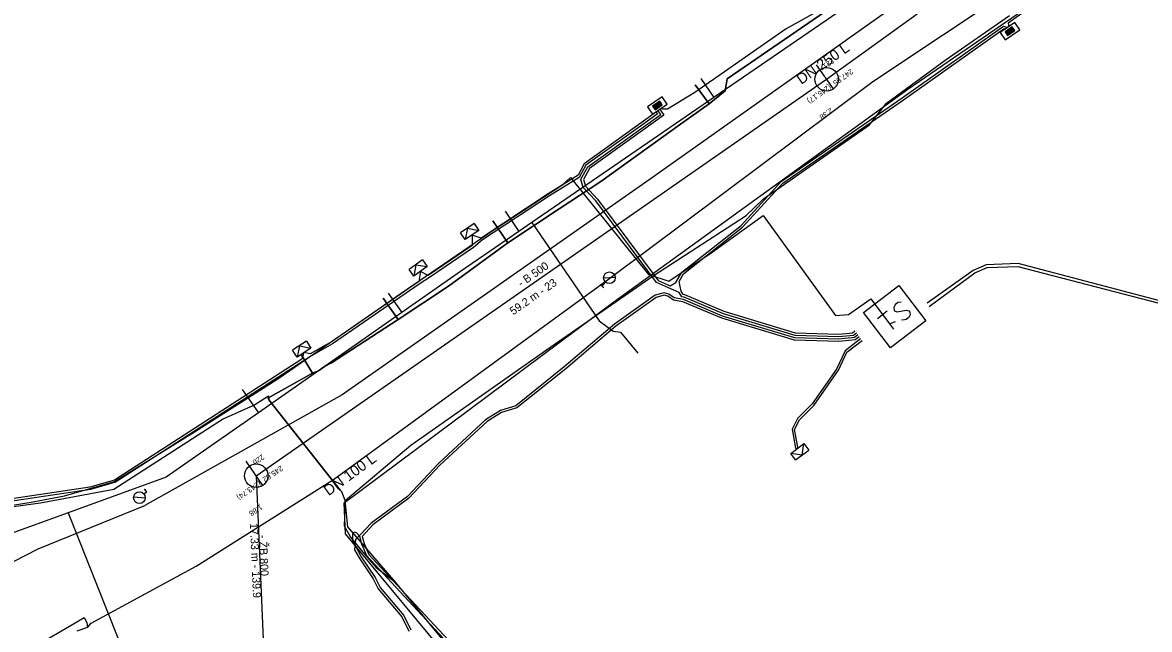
# Model space of a CAD drawing. Extents: x -600636 to -600148, y -1203980 to -1203569.
# Drawn here: x -600579.1 to -600483.1, y -1203791.8 to -1203740.1 of the extents above; entities that cross this region are included whole.
import ezdxf

# ---------------------------------------------------------------- set-up
doc = ezdxf.new("R2010")
doc.units = 0
for name, color, linetype in [('Cetin zam průběh', 7, 'Continuous'), ('EON objekty', 7, 'Continuous'), ('EON podzemní NN', 7, 'Continuous'), ('EON podzemní VN', 7, 'Continuous'), ('GasNet NTL', 7, 'Continuous'), ('Implicitní', 7, 'Continuous'), ('VaK Břeclav_kanalizace', 7, 'Continuous'), ('Vak Břeclav_vodovod', 7, 'Continuous'), ('Vrstva 6', 7, 'Continuous'), ('Vrstva 9', 7, 'Continuous')]:
    doc.layers.add(name, color=color, linetype=linetype)

# ---------------------------------------------------------------- blocks, each defined once
blk = doc.blocks.new('NN630')
at = {"layer": 'Vrstva 9'}
for points in [[(-0.003, -0.7), (-0.703, 0)], [(-0.703, -0.7), (-0.703, 0), (0.697, 0), (0.697, -0.7)], [(-0.703, -0.7), (0.697, -0.7)], [(-0.003, -0.7), (0.697, 0)]]:
    blk.add_lwpolyline(points, dxfattribs=at)
blk = doc.blocks.new('NN620')
at = {"layer": 'EON objekty'}
for points in [[(0.752, 0.004), (-0.748, 0.004)], [(-0.748, 0.004), (-0.748, -0.746)], [(0.752, -0.746), (0.752, 0.004)], [(-0.748, -0.746), (0.752, -0.746)], [(0.368, -0.18), (-0.376, -0.18)], [(-0.376, -0.18), (-0.376, -0.558)], [(-0.376, -0.558), (0.368, -0.558)], [(0.321, -0.227), (-0.329, -0.227)], [(-0.329, -0.227), (-0.329, -0.51)], [(-0.329, -0.51), (0.321, -0.51)], [(0.274, -0.274), (-0.281, -0.274)], [(-0.281, -0.274), (-0.281, -0.463)], [(-0.281, -0.463), (0.274, -0.463)], [(0.227, -0.321), (-0.234, -0.321)], [(-0.234, -0.321), (-0.234, -0.416)], [(-0.234, -0.416), (0.227, -0.416)], [(-0.193, -0.369), (0.185, -0.369)], [(0.227, -0.416), (0.227, -0.321)], [(0.274, -0.463), (0.274, -0.274)], [(0.321, -0.51), (0.321, -0.227)], [(0.368, -0.558), (0.368, -0.18)]]:
    blk.add_lwpolyline(points, dxfattribs=at)
blk = doc.blocks.new('VN640')
at = {"layer": 'Vrstva 6'}
for points in [[(-1.89, 1.889), (1.889, 1.889)], [(-1.89, -1.89), (-1.89, 1.889)], [(1.889, 1.889), (1.889, -1.89)], [(-1.26, 0.787), (-0.221, 0.787)], [(-0.725, 0.787), (-0.725, -0.788)], [(1.197, 0.661), (0.945, 0.787), (0.661, 0.787), (0.409, 0.661), (0.283, 0.472), (0.283, 0.409), (0.409, 0.22), (1.133, -0.158), (1.259, -0.316), (1.259, -0.473), (1.133, -0.662), (0.913, -0.788), (0.629, -0.788), (0.503, -0.725), (0.283, -0.599)], [(1.889, -1.89), (-1.89, -1.89)]]:
    blk.add_lwpolyline(points, dxfattribs=at)
blk = doc.blocks.new('MoSymbol 2')
at = {"layer": 'Implicitní'}
blk.add_line((0, 0.0005), (0, -0.00075), dxfattribs=at)
blk.add_circle((0, 0), 0.0005, dxfattribs=at)
blk = doc.blocks.new('MoSymbol 3')
at = {"layer": 'Implicitní'}
for p, q in [((-0.000365, -0.000365), (0.000365, 0.000365)), ((-0.000225, 0.00095), (0.000225, 0.00095)), ((0, 0.00095), (0, 0.0005))]:
    blk.add_line(p, q, dxfattribs=at)
blk.add_circle((0, 0), 0.0005, dxfattribs=at)
blk = doc.blocks.new('MoSymbol 4')
at = {"layer": 'Implicitní'}
for p, q in [((-0.000365, -0.000365), (0.000365, 0.000365)), ((0.0003, -0.0008), (0.0002, -0.00085))]:
    blk.add_line(p, q, dxfattribs=at)
blk.add_lwpolyline([(0, -0.0005), (0, -0.0008), (0.0003, -0.0008), (0.0002, -0.00075)], dxfattribs=at)
blk.add_circle((0, 0), 0.0005, dxfattribs=at)

msp = doc.modelspace()

# ---------------------------------------------------------------- linework, layer by layer
at = {"layer": 'Cetin zam průběh'}
for points in [[(-600506.23, -1203736.22), (-600510.74, -1203739.23), (-600519.05, -1203744.93), (-600519.22, -1203745.96), (-600520.6, -1203747.08), (-600523.03, -1203748.81), (-600529.84, -1203753.68), (-600533.39, -1203756), (-600537.76, -1203758.9), (-600542.81, -1203762.61), (-600547.1, -1203765.43), (-600552.78, -1203769.13), (-600553.37, -1203769.45), (-600553.89, -1203769.82), (-600554.42, -1203770.01), (-600558.01, -1203772.02)], [(-600499.06, -1203830.56), (-600501.19, -1203829.34), (-600520.52, -1203816.59), (-600528.18, -1203809.84), (-600537.51, -1203800.68), (-600551.58, -1203783.7), (-600551.71, -1203781.06), (-600528.73, -1203763.94), (-600503.65, -1203745.81), (-600492.34, -1203738.04), (-600490.82, -1203737.26)], [(-600551.61, -1203780.87), (-600546.02, -1203776.14), (-600534.46, -1203768.01), (-600525.37, -1203761.73), (-600517.43, -1203756.57), (-600515.95, -1203755.15), (-600506.94, -1203748.87), (-600505.47, -1203747), (-600500.48, -1203743.35), (-600495, -1203739.53)], [(-600520.6, -1203747.08), (-600519.22, -1203745.96), (-600519.05, -1203744.93), (-600510.74, -1203739.23)], [(-600521.78, -1203745.45), (-600520.6, -1203747.08)], [(-600520.6, -1203747.08), (-600521.78, -1203745.45)], [(-600537.76, -1203758.9), (-600533.39, -1203756), (-600529.84, -1203753.68), (-600523.03, -1203748.81), (-600520.6, -1203747.08)], [(-600539.032, -1203757.042), (-600537.76, -1203758.9)], [(-600537.76, -1203758.9), (-600539.032, -1203757.042)], [(-600547.1, -1203765.43), (-600542.81, -1203762.61), (-600537.76, -1203758.9)], [(-600548.377, -1203763.622), (-600547.1, -1203765.43)], [(-600547.1, -1203765.43), (-600548.377, -1203763.622)], [(-600553.37, -1203769.45), (-600552.78, -1203769.13), (-600547.1, -1203765.43)], [(-600555.386, -1203768.434), (-600554.42, -1203770.01)], [(-600554.42, -1203770.01), (-600555.386, -1203768.434)], [(-600558.18, -1203772.12), (-600558.01, -1203772.02), (-600554.42, -1203770.01)], [(-600554.42, -1203770.01), (-600553.89, -1203769.82), (-600553.37, -1203769.45)], [(-600587.64, -1203782.42), (-600577.59, -1203781.05), (-600571.34, -1203779.9), (-600562.09, -1203773.93), (-600559.42, -1203772.74), (-600558.16, -1203771.94), (-600558.14, -1203772.28)], [(-600558.14, -1203772.28), (-600558.18, -1203772.12)], [(-600558.14, -1203772.28), (-600552.05, -1203779.98)], [(-600551.61, -1203780.87), (-600551.92, -1203780.12), (-600552.05, -1203779.98), (-600558.14, -1203772.28)], [(-600577.59, -1203781.05), (-600571.34, -1203779.9)], [(-600551.61, -1203780.87), (-600551.71, -1203783.02)], [(-600547.3, -1203787.83), (-600551.39, -1203783.09), (-600551.61, -1203780.87)], [(-600551.71, -1203783.02), (-600551.17, -1203783.97)], [(-600551.17, -1203783.97), (-600549.98, -1203785.44)], [(-600549.98, -1203785.44), (-600548.99, -1203786.57)], [(-600548.99, -1203786.57), (-600547.3, -1203787.83)], [(-600531.56, -1203806.25), (-600532.29, -1203804.48), (-600533.68, -1203802.64), (-600539.8, -1203796.23), (-600541.55, -1203794.83), (-600547.3, -1203787.83)]]:
    msp.add_lwpolyline(points, dxfattribs=at)
at = {"layer": 'EON podzemní NN'}
for points in [[(-600492.79, -1203738.54), (-600495.12, -1203740.2), (-600495.048, -1203740.497)], [(-600510.522, -1203738.712), (-600514.041, -1203740.671), (-600521.805, -1203746.093), (-600524.15, -1203747.521), (-600524.559, -1203747.517), (-600524.638, -1203747.401)], [(-600524.803, -1203747.515), (-600524.45, -1203748.027), (-600525.161, -1203748.537), (-600530.795, -1203752.578), (-600531.314, -1203753.511), (-600531.149, -1203754.093), (-600530.101, -1203755.202), (-600524.951, -1203762.125), (-600523.912, -1203762.574), (-600523.438, -1203762.281), (-600522.938, -1203761.404), (-600517.882, -1203757.418), (-600514.454, -1203753.685), (-600504.155, -1203746.549), (-600495.501, -1203740.461), (-600495.161, -1203740.575)], [(-600508.174, -1203766.439), (-600508.374, -1203766.595), (-600509.556, -1203766.723), (-600513.237, -1203766.614), (-600519.313, -1203764.765), (-600522.658, -1203763.34), (-600522.814, -1203763.315), (-600522.985, -1203763.029), (-600523.058, -1203762.627), (-600523.155, -1203762.189), (-600522.784, -1203761.536), (-600517.746, -1203757.566), (-600514.322, -1203753.837), (-600504.041, -1203746.713), (-600495.441, -1203740.663), (-600495.347, -1203740.703)], [(-600525.132, -1203747.742), (-600525.004, -1203747.932), (-600525.449, -1203748.251), (-600531.101, -1203752.305), (-600531.678, -1203753.342), (-600534.216, -1203754.907), (-600539.903, -1203758.664), (-600540.687, -1203759.293), (-600544.438, -1203761.852), (-600545.238, -1203762.368), (-600552.695, -1203767.501), (-600554.501, -1203768.539), (-600555.203, -1203768.985), (-600571.205, -1203779.307), (-600573.331, -1203779.913), (-600584.423, -1203781.578), (-600586.99, -1203781.825)], [(-600525.297, -1203747.856), (-600525.279, -1203747.883), (-600531.254, -1203752.169), (-600531.757, -1203753.151), (-600534.324, -1203754.739), (-600540.021, -1203758.502), (-600540.809, -1203758.243), (-600540.807, -1203759.133), (-600544.548, -1203761.686), (-600545.191, -1203761.339), (-600545.348, -1203762.202), (-600552.801, -1203767.331), (-600554.605, -1203768.367), (-600555.135, -1203768.259), (-600555.311, -1203768.817), (-600571.289, -1203779.123), (-600573.373, -1203779.717), (-600584.447, -1203781.38), (-600586.729, -1203781.599)], [(-600508.051, -1203766.597), (-600508.296, -1203766.788), (-600509.548, -1203766.923), (-600513.27, -1203766.813), (-600519.381, -1203764.953), (-600522.714, -1203763.534), (-600522.937, -1203763.499), (-600523.15, -1203763.143), (-600524.054, -1203762.728), (-600525.079, -1203762.287), (-600530.255, -1203755.33), (-600531.329, -1203754.195), (-600531.529, -1203753.485), (-600530.948, -1203752.441), (-600524.726, -1203747.979), (-600524.968, -1203747.629)], [(-600507.93, -1203766.757), (-600508.218, -1203766.98), (-600509.54, -1203767.123), (-600513.302, -1203767.013), (-600519.449, -1203765.141), (-600522.77, -1203763.728), (-600523.568, -1203763.602), (-600524.04, -1203763.278), (-600524.429, -1203763.174), (-600525.201, -1203763.374), (-600528.66, -1203765.841), (-600532.953, -1203769.48), (-600537.072, -1203772.794), (-600538.387, -1203773.179), (-600539.651, -1203773.979), (-600543.651, -1203777.673), (-600546.318, -1203780.515), (-600549.403, -1203782.78), (-600550.274, -1203783.739), (-600550.742, -1203784.175), (-600550.814, -1203785.049), (-600550.442, -1203785.747), (-600549.233, -1203787.52), (-600548.817, -1203788.369), (-600546.802, -1203790.768), (-600546.203, -1203791.975)], [(-600507.807, -1203766.914), (-600508.14, -1203767.173), (-600509.532, -1203767.323), (-600513.335, -1203767.212), (-600519.517, -1203765.329), (-600522.826, -1203763.922), (-600523.644, -1203763.792), (-600524.125, -1203763.462), (-600524.429, -1203763.38), (-600525.115, -1203763.558), (-600528.538, -1203765.999), (-600532.825, -1203769.634), (-600536.978, -1203772.974), (-600538.303, -1203773.363), (-600539.529, -1203774.139), (-600543.511, -1203777.815), (-600546.184, -1203780.665), (-600549.269, -1203782.93), (-600550.165, -1203783.917), (-600550.015, -1203784.513), (-600549.597, -1203785.445), (-600546.825, -1203788.464), (-600540.809, -1203794.912)], [(-600507.684, -1203767.072), (-600509.013, -1203768.103), (-600509.737, -1203769.669), (-600511.828, -1203772.631), (-600513.052, -1203773.88), (-600513.528, -1203774.769), (-600513.229, -1203776.405), (-600513.085, -1203776.425), (-600513.041, -1203776.319), (-600513.318, -1203774.801), (-600512.89, -1203774), (-600511.674, -1203772.759), (-600509.563, -1203769.769), (-600508.852, -1203768.232), (-600507.561, -1203767.229)], [(-600540.961, -1203795.042), (-600546.971, -1203788.6), (-600549.767, -1203785.557), (-600550.205, -1203784.579), (-600550.366, -1203783.937), (-600550.644, -1203783.623), (-600550.862, -1203783.55), (-600550.993, -1203783.691), (-600551.002, -1203784.225), (-600550.27, -1203785.645), (-600549.059, -1203787.42), (-600548.649, -1203788.259), (-600546.634, -1203790.658), (-600546.033, -1203791.869)]]:
    msp.add_lwpolyline(points, dxfattribs=at)
at = {"layer": 'EON podzemní VN'}
for points in [[(-600587.683, -1203782.424), (-600583.35, -1203781.8), (-600578.39, -1203781.01), (-600575.54, -1203780.47), (-600571.28, -1203779.25), (-600564.47, -1203775), (-600557.37, -1203770.49), (-600546.85, -1203763.19), (-600538.93, -1203757.78), (-600533.07, -1203753.94), (-600532.42, -1203753.34), (-600525.77, -1203761.6), (-600524.04, -1203762.18), (-600520.34, -1203759.69), (-600515.99, -1203756.58), (-600509.828, -1203765.1), (-600508.705, -1203765.014), (-600506.819, -1203763.668), (-600505.22, -1203765.813), (-600504.7, -1203765.596)], [(-600480.143, -1203764.381), (-600494.25, -1203760.681), (-600496.996, -1203760.787), (-600498.081, -1203761.253), (-600502, -1203764.039)], [(-600501.847, -1203764.325), (-600497.959, -1203761.475), (-600496.908, -1203761.001), (-600494.282, -1203760.923), (-600480.162, -1203764.577), (-600479.132, -1203764.829), (-600476.382, -1203766.071), (-600473.11, -1203766.482), (-600465.75, -1203768.323), (-600457.511, -1203769.594), (-600456.508, -1203769.518), (-600454.624, -1203770.445), (-600451.211, -1203771.488), (-600448.233, -1203771.815), (-600444.486, -1203774.019), (-600442.217, -1203775.59), (-600438.167, -1203778.496), (-600424.472, -1203787.735), (-600416.801, -1203792.528), (-600411.123, -1203796.487), (-600404.975, -1203801.537), (-600404.82, -1203801.644), (-600404.96, -1203802.62)]]:
    msp.add_lwpolyline(points, dxfattribs=at)
at = {"layer": 'GasNet NTL'}
for points in [[(-600486.68, -1203722.48), (-600489.25, -1203724.39), (-600497.78, -1203730.73), (-600501.03, -1203733.15), (-600504.95, -1203736.06), (-600509.64, -1203739.28), (-600520.2, -1203746.52), (-600535.72, -1203757.18), (-600536.81, -1203757.93), (-600541.8, -1203761.35), (-600546.79, -1203764.85), (-600559, -1203773.38), (-600566.88, -1203778.88), (-600575.24, -1203781.91), (-600588.36, -1203786.65), (-600589.51, -1203786.96)], [(-600521.31, -1203744.92), (-600520.2, -1203746.52)], [(-600537.99, -1203756.21), (-600536.81, -1203757.93)], [(-600535.72, -1203757.18), (-600529.98, -1203765.55), (-600528.77, -1203766.42), (-600528.15, -1203766.53), (-600526.67, -1203768.32)], [(-600547.95, -1203763.19), (-600546.79, -1203764.85)], [(-600560.39, -1203771.4), (-600559, -1203773.38)], [(-600575.24, -1203781.91), (-600569.42, -1203796.55), (-600565.52, -1203798.53), (-600556.3, -1203803.23), (-600544.92, -1203810.5), (-600533.6, -1203818.43), (-600528.85, -1203821.76), (-600523.82, -1203825.28), (-600521.43, -1203826.96)]]:
    msp.add_lwpolyline(points, dxfattribs=at)
at = {"layer": 'VaK Břeclav_kanalizace'}
for p, q in [((-600510.583, -1203744.976), (-600486.459, -1203727.53)), ((-600559.203, -1203778.746), (-600510.583, -1203744.976)), ((-600559.203, -1203778.746), (-600558.458, -1203796.062))]:
    msp.add_line(p, q, dxfattribs=at)
at = {"layer": 'Vak Břeclav_vodovod'}
msp.add_line((-600573.583, -1203791.689), (-600574.494, -1203791.995), dxfattribs=at)
for points in [[(-600454.254, -1203701.013), (-600472.203, -1203715.152), (-600488.658, -1203727.344), (-600496.91, -1203733.124), (-600525.432, -1203753.341), (-600551.886, -1203771.847), (-600568.695, -1203781.296)], [(-600529.075, -1203761.905), (-600506.647, -1203745.162), (-600494.673, -1203737.188), (-600466.586, -1203717.369), (-600450.006, -1203704.697)], [(-600573.583, -1203791.689), (-600573.278, -1203791.312), (-600564.325, -1203786.439), (-600552.62, -1203779.071), (-600529.075, -1203761.905)], [(-600612.162, -1203773.201), (-600602.995, -1203784.637), (-600601.189, -1203803.343), (-600600.899, -1203803.294), (-600597.986, -1203803.077), (-600584.599, -1203797.079), (-600575.117, -1203791.572), (-600573.857, -1203790.834), (-600573.636, -1203791.26), (-600573.583, -1203791.689)], [(-600600.849, -1203803.933), (-600600.899, -1203803.294), (-600601.584, -1203796.186), (-600600.078, -1203795.751), (-600587.99, -1203790.2), (-600577.783, -1203784.972), (-600568.695, -1203781.296)]]:
    msp.add_lwpolyline(points, dxfattribs=at)

# ---------------------------------------------------------------- block references
at = {"layer": 'EON podzemní NN'}
for name, p, rotation in [('NN620', (-600495.16, -1203740.575), 34.499191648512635), ('NN620', (-600524.804, -1203747.514), -145.40948332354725), ('NN630', (-600540.809, -1203758.243), -145.68219166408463), ('NN630', (-600545.191, -1203761.339), -144.19583613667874), ('NN630', (-600555.135, -1203768.259), -146.84598330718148), ('NN630', (-600513.085, -1203776.425), 36.87192492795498)]:
    msp.add_blockref(name, p, dxfattribs=dict(at, rotation=rotation))
at = {"layer": 'EON podzemní VN', "rotation": 37.35362222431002}
msp.add_blockref('VN640', (-600504.779, -1203765.202), dxfattribs=at)
at = {"layer": 'VaK Břeclav_kanalizace'}
for p, xscale, yscale, rotation in [((-600510.583, -1203744.976), 1999.750031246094, 1999.7500312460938, -144.72778475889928), ((-600559.203, -1203778.746), 1999.7500312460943, 1999.7500312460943, -145.4726226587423)]:
    msp.add_blockref('MoSymbol 2', p, dxfattribs=dict(at, xscale=xscale, yscale=yscale, rotation=rotation))
at = {"layer": 'Vak Břeclav_vodovod'}
for name, p, xscale, yscale, rotation in [('MoSymbol 3', (-600529.097, -1203761.885), 999.875015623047, 999.8750156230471, 138.37882730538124), ('MoSymbol 4', (-600569.159, -1203780.618), 999.8750156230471, 999.875015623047, 129.01940047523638)]:
    msp.add_blockref(name, p, dxfattribs=dict(at, xscale=xscale, yscale=yscale, rotation=rotation))

# ---------------------------------------------------------------- texts
at = {"layer": 'VaK Břeclav_kanalizace'}
for s, height, rotation, p in [('221', 0.4549, 215.27222, (-600510.132, -1203743.157)), ('247,55  (245,17)', 0.45494, 215.27222, (-600508.529, -1203744.066)), ('2.38', 0.4549, 215.27222, (-600510.253, -1203747.385)), ('- B 500', 0.6824, 34.78271, (-600536.621, -1203762.71)), ('59.2 m - 23', 0.68241, 34.78271, (-600537.3, -1203765.094)), ('22b', 0.4549, 214.52738, (-600558.703, -1203776.902)), ('245,62  (243,74)', 0.45494, 214.52738, (-600557.123, -1203777.863)), ('1.88', 0.4549, 214.52738, (-600558.863, -1203781.16)), ('17.33 m - 139.9', 0.68241, 272.46301, (-600559.746, -1203782.79)), ('- ŽB 800', 0.6824, 272.46301, (-600558.973, -1203783.805))]:
    msp.add_text(s, height=height, rotation=rotation, dxfattribs=at).set_placement(p)
at = {"layer": 'Vak Břeclav_vodovod'}
for s, rotation, p in [('DN 250 L', 35.32983, (-600512.741, -1203745.461)), ('DN 100 L', 36.09474, (-600553.032, -1203780.497))]:
    msp.add_text(s, height=0.9099, rotation=rotation, dxfattribs=at).set_placement(p)

doc.saveas('drawing.dxf')
